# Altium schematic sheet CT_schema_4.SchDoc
size 334 x 183 mm
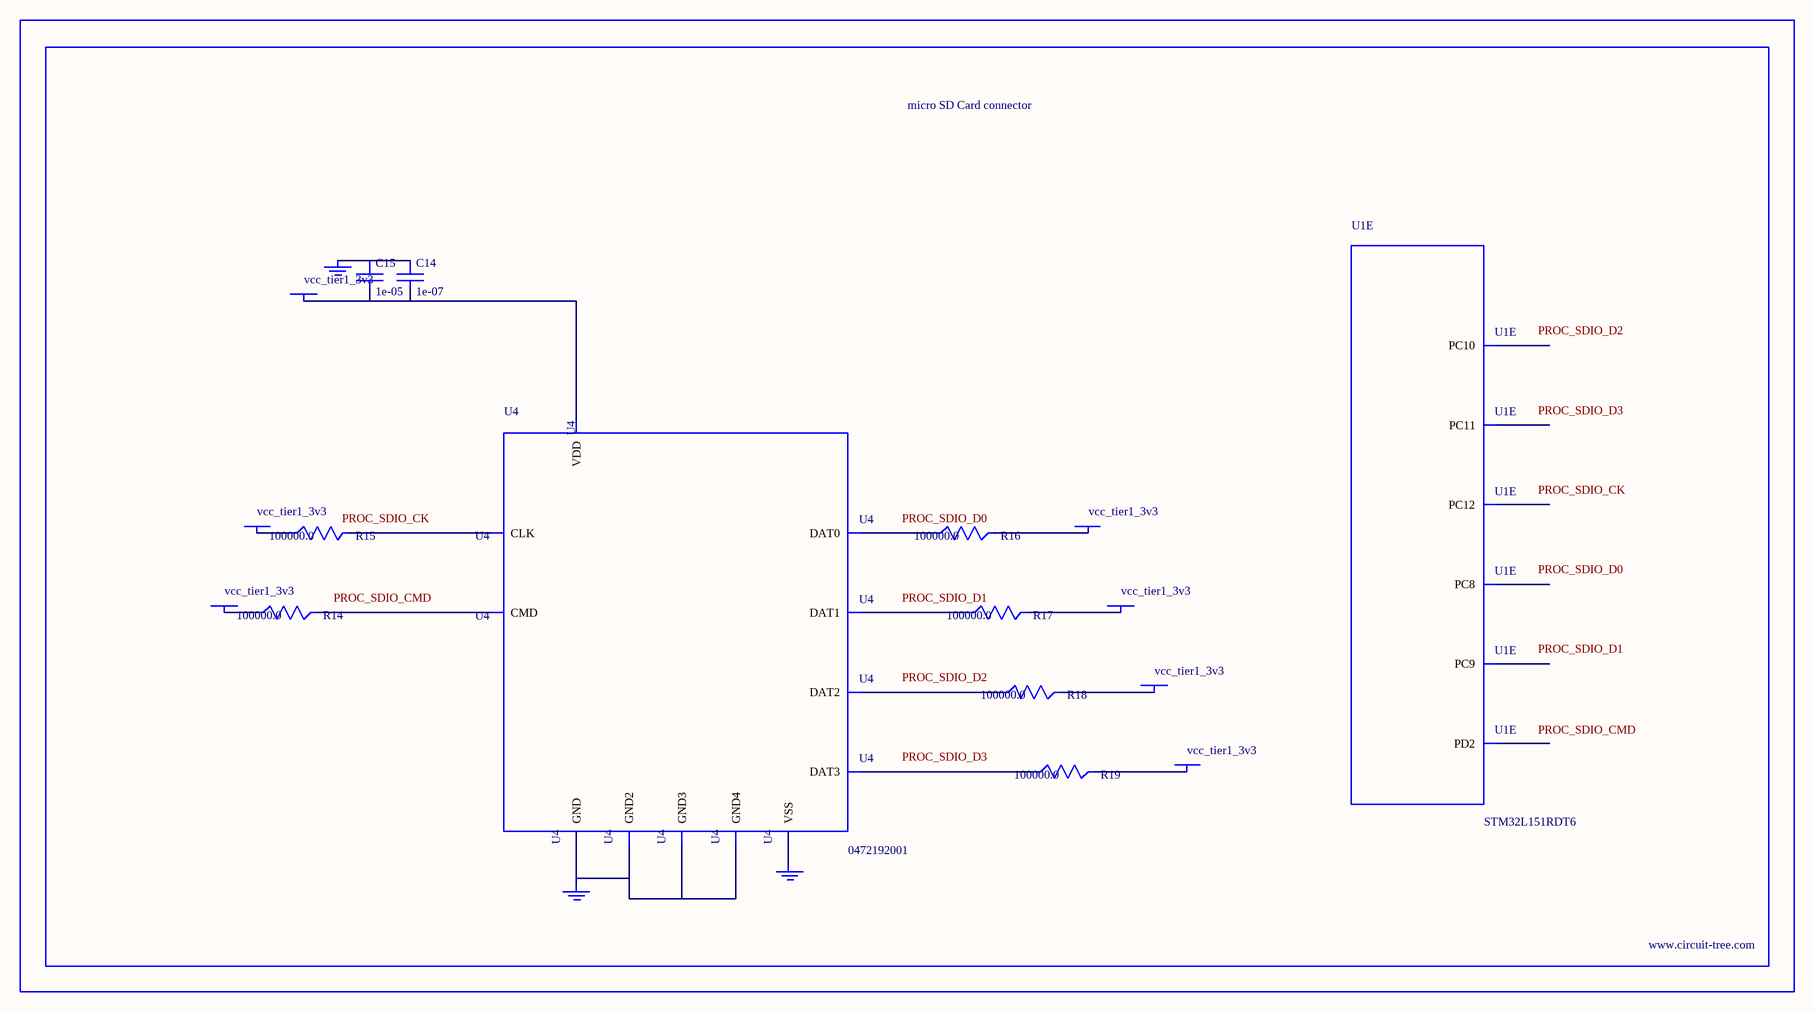
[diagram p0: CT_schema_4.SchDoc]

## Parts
BORDER3  (no value)
C14  1e-07  [C0402]
C15  1e-05  [C0805]
GND_INSTANCE_3_0  (no value)
GND_INSTANCE_3_1  (no value)
GND_INSTANCE_3_2  (no value)
POWER_INSTANCE_3_0  vcc_tier1_3v3
POWER_INSTANCE_3_1  vcc_tier1_3v3
POWER_INSTANCE_3_2  vcc_tier1_3v3
POWER_INSTANCE_3_3  vcc_tier1_3v3
POWER_INSTANCE_3_4  vcc_tier1_3v3
POWER_INSTANCE_3_5  vcc_tier1_3v3
POWER_INSTANCE_3_6  vcc_tier1_3v3
R14  100000.0  [R0603]
R15  100000.0  [R0603]
R16  100000.0  [R0603]
R17  100000.0  [R0603]
R18  100000.0  [R0603]
R19  100000.0  [R0603]
U1  STM32L151RDT6  [LQFP64]  (part E of 7)
U4  0472192001  [MOLEX_47219-2001]

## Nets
NetC14_1: C14.1 C15.1 GND_INSTANCE_3_0.0(GND)
NetC14_2: C14.2 C15.2 POWER_INSTANCE_3_3.0(PWR) U4.4(VDD)
NetGND_INSTANCE_3_1_0: GND_INSTANCE_3_1.0(GND) U4.6(VSS)
NetGND_INSTANCE_3_2_0: GND_INSTANCE_3_2.0(GND) U4.G1(GND) U4.G2(GND2) U4.G3(GND3) U4.G4(GND4)
NetPOWER_INSTANCE_3_0_0: POWER_INSTANCE_3_0.0(PWR) R18.2
NetPOWER_INSTANCE_3_1_0: POWER_INSTANCE_3_1.0(PWR) R19.2
NetPOWER_INSTANCE_3_2_0: POWER_INSTANCE_3_2.0(PWR) R14.1
NetPOWER_INSTANCE_3_4_0: POWER_INSTANCE_3_4.0(PWR) R15.1
NetPOWER_INSTANCE_3_5_0: POWER_INSTANCE_3_5.0(PWR) R16.2
NetPOWER_INSTANCE_3_6_0: POWER_INSTANCE_3_6.0(PWR) R17.2
NetR14_2: R14.2 U4.3(CMD)
NetR15_2: R15.2 U4.5(CLK)
NetR16_1: R16.1 U4.7(DAT0)
NetR17_1: R17.1 U4.8(DAT1)
NetR18_1: R18.1 U4.1(DAT2)
NetR19_1: R19.1 U4.2(DAT3)

Not connected (* = marked no-connect by the designer): U1 39(PC8) 40(PC9) 51(PC10) 52(PC11) 53(PC12) 54(PD2)

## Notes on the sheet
- Labels drawn without touching a wire or pin: PROC_SDIO_CK, PROC_SDIO_CMD, PROC_SDIO_D0, PROC_SDIO_D1, PROC_SDIO_D2, PROC_SDIO_D3

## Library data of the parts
BORDER3 = BORDER_PAGE3
C14 = C0402C104K3RACTU
C15 = C0805C106K8RACTU
GND_INSTANCE_3_0-GND_INSTANCE_3_2 = GND
POWER_INSTANCE_3_0-POWER_INSTANCE_3_6 = PWR
R14-R19 = RC0603JR-07100KL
